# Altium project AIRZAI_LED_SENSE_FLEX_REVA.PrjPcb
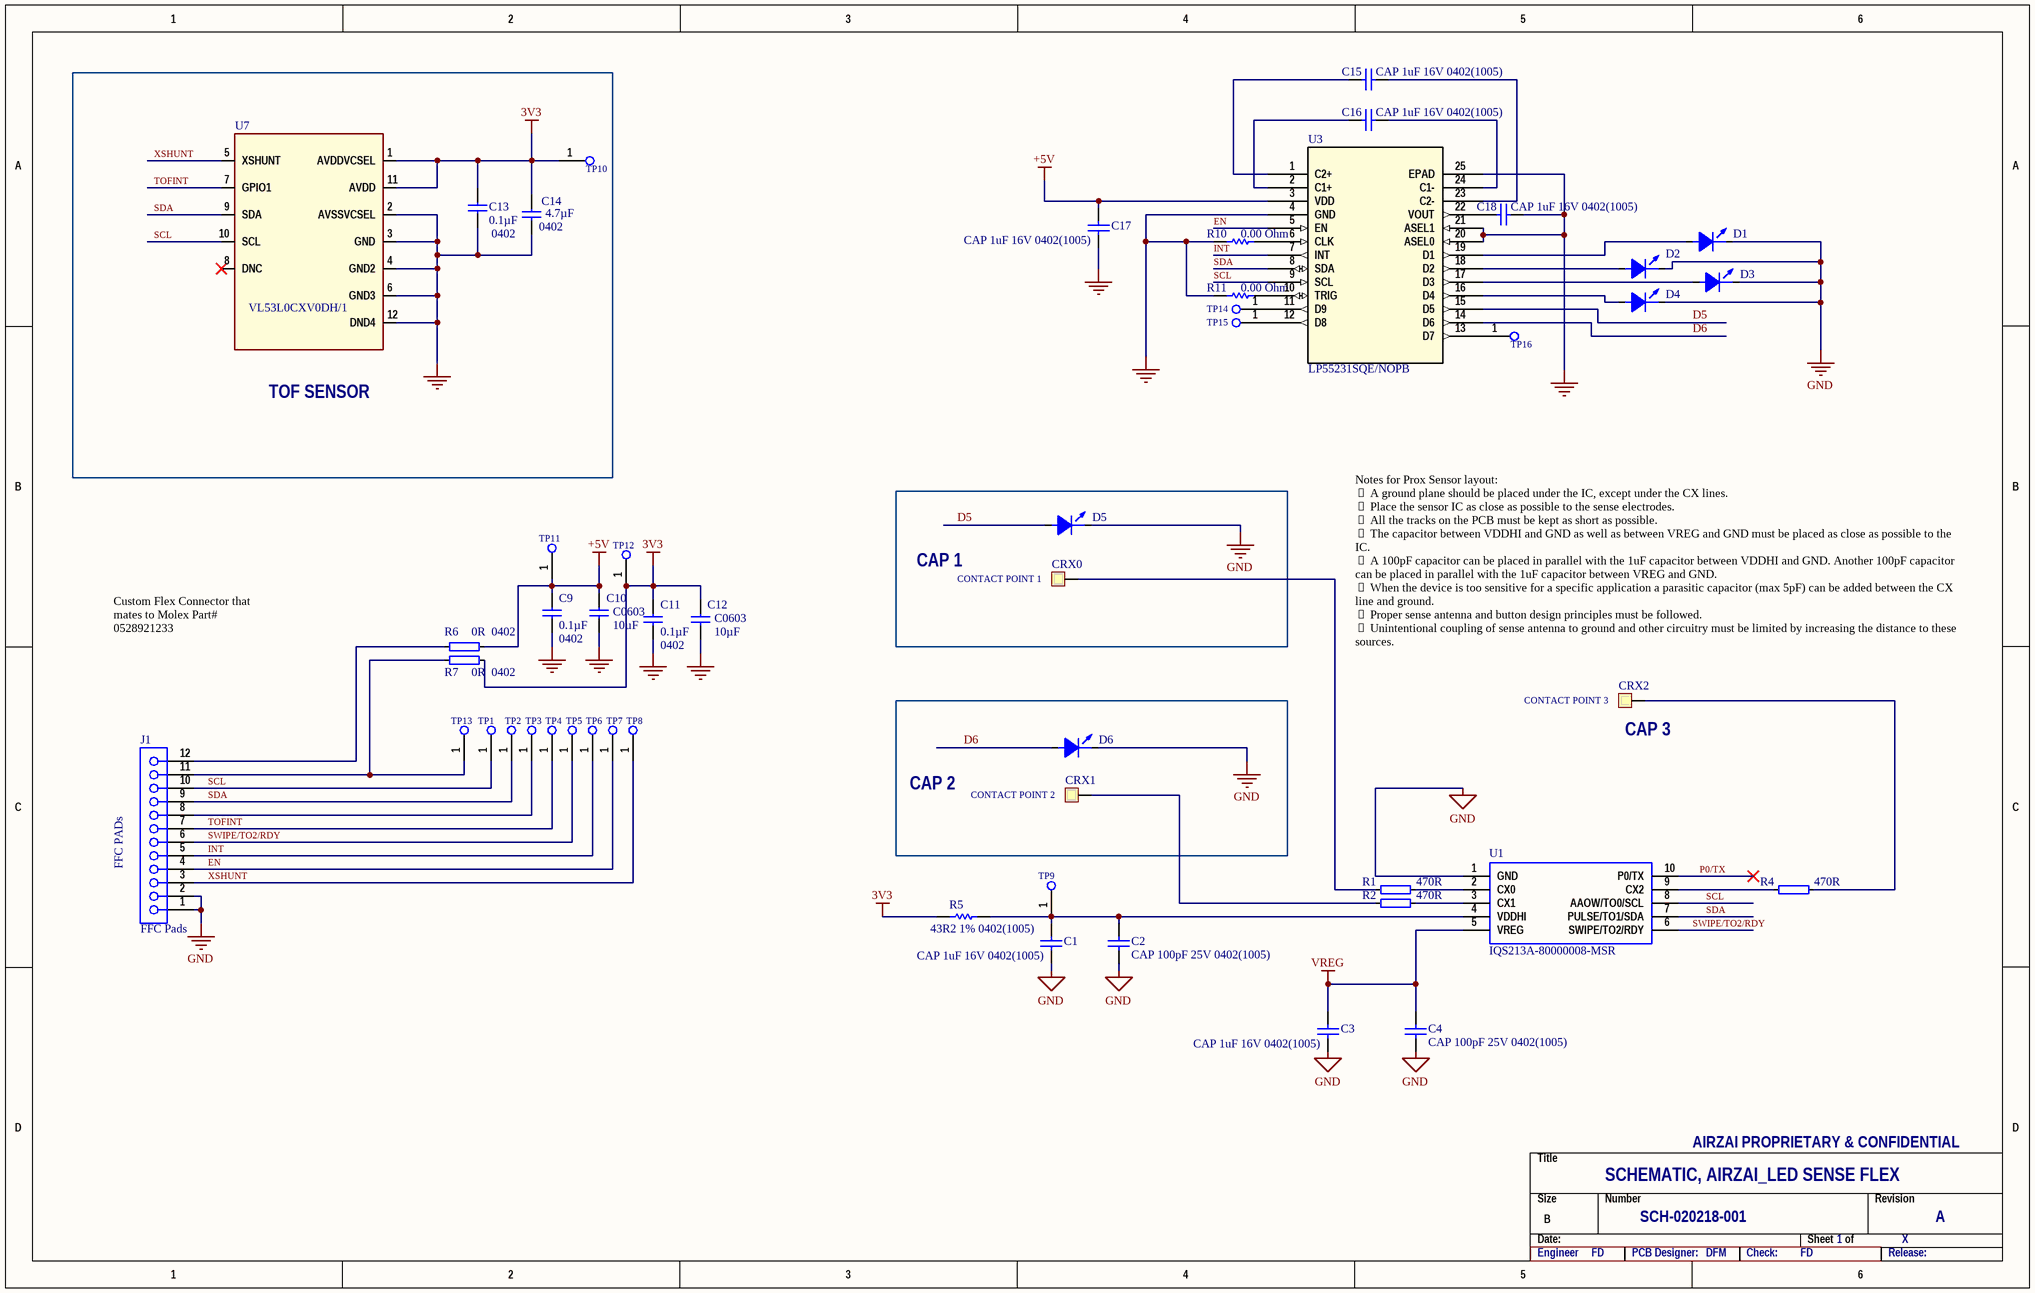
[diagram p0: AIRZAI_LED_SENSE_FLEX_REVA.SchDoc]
1 sheet, 51 parts. Net scope: global (net labels, ports and power ports of the same name join across sheets).
Board file: AIRZAI_LED_SENSE_FLEX_REVA.PcbDoc

## Sheet AIRZAI_LED_SENSE_FLEX_REVA.SchDoc
size B

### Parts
C1  CAP 1uF 16V 0402(1005)  [0402-A]
C2  CAP 100pF 25V 0402(1005)  [0402-A]
C3  CAP 1uF 16V 0402(1005)  [0402-A]
C4  CAP 100pF 25V 0402(1005)  [0402-A]
C9  0.1µF  Footprint: 0402  [0402CAP]
C10  10µF  Footprint: C0603  [0603]
C11  0.1µF  Footprint: 0402  [0402CAP]
C12  10µF  Footprint: C0603  [0603]
C13  0.1µF  Footprint: 0402  [0402CAP]
C14  4.7µF  Footprint: 0402  [0603]
C15  CAP 1uF 16V 0402(1005)  [CAPC0402(1005)60_M]
C16  CAP 1uF 16V 0402(1005)  [CAPC0402(1005)60_M]
C17  CAP 1uF 16V 0402(1005)  [CAPC0402(1005)60_M]
C18  CAP 1uF 16V 0402(1005)  [CAPC0402(1005)60_M]
CRX0  CONTACT POINT 1  [CONTACT_POINT_1CM _SQ]
CRX1  CONTACT POINT 2  [CONTACT_POINT_1CM _SQ]
CRX2  CONTACT POINT 3  [CONTACT_POINT_0.7CM]
D1  WHITE  [LED1206_LTW-C230DS]  (value not drawn)
D2  WHITE  [LED1206_LTW-C230DS]  (value not drawn)
D3  WHITE  [LED1206_LTW-C230DS]  (value not drawn)
D4  WHITE  [LED1206_LTW-C230DS]  (value not drawn)
D5  WHITE  [LED1206_LTW-C230DS]  (value not drawn)
D6  WHITE  [LED1206_LTW-C230DS]  (value not drawn)
J1  FFC Pads  [FFC_Pads]
R1  470R  [0402-A]
R2  470R  [0402-A]
R4  470R  [0402-A]
R5  43R2 1% 0402(1005)  [0402-A]
R6  0R  [0402]
R7  0R  [0402]
R10  value 0.00 Ohm  [0402]  (hidden comment: Jumper 0402(1005))
R11  value 0.00 Ohm  [0402]  (hidden comment: Jumper 0402(1005))
TP1  Test Point  [TP_0.9MM]  (value not drawn)
TP2  Test Point  [TP_0.9MM]  (value not drawn)
TP3  Test Point  [TP_0.9MM]  (value not drawn)
TP4  Test Point  [TP_0.9MM]  (value not drawn)
TP5  Test Point  [TP_0.9MM]  (value not drawn)
TP6  Test Point  [TP_0.9MM]  (value not drawn)
TP7  Test Point  [TP_0.9MM]  (value not drawn)
TP8  Test Point  [TP_0.9MM]  (value not drawn)
TP9  Test Point  [TP_0.9MM]  (value not drawn)
TP10  Test Point  [TP_0.9MM]  (value not drawn)
TP11  Test Point  [TP_0.9MM]  (value not drawn)
TP12  Test Point  [TP_0.9MM]  (value not drawn)
TP13  Test Point  [TP_0.9MM]  (value not drawn)
TP14  Test Point  [TP_0.9MM]  (value not drawn)
TP15  Test Point  [TP_0.9MM]  (value not drawn)
TP16  Test Point  [TP_0.9MM]  (value not drawn)
U1  IQS213A-80000008-MSR  [MSOP-10-IQS213A-80000008-MSR]
U3  LP55231SQE/NOPB  [WQFN-24-LP55231SQE/NOPB]
U7  VL53L0CXV0DH/1  [VL53L0X]

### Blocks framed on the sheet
TOF SENSOR: C13 C14 TP10 U7
CAP 1: CRX0 D5
CAP 2: CRX1 D6

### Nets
3V3: C11.1 C12.1 C13.1 C14.2 R5.1 R7.1 TP10.1 TP12.1 U7.1(AVDDVCSEL) U7.11(AVDD)
+5V: C9.1 C10.1 C17.2 R6.1 TP11.1 U3.3(VDD)
GND: C1.1 C2.1 C3.1 C4.1 C9.2 C10.2 C11.2 C12.2 C13.2 C14.1 C17.1 C18.2 D1.1(CATHODE) D2.1(CATHODE) D3.1(CATHODE) D4.1(CATHODE) D5.1(CATHODE) D6.1(CATHODE) J1.1 J1.2 R10.1 R11.1 U1.1(GND) U3.4(GND) U3.20(ASEL0) U3.21(ASEL1) U3.25(EPAD) U7.2(AVSSVCSEL) U7.3(GND) U7.4(GND2) U7.6(GND3) U7.12(DND4)
VREG: C3.2 C4.2 U1.5(VREG)
D5: D5.2(ANODE) U3.15(D5)
D6: D6.2(ANODE) U3.14(D6)
EN: J1.4 TP7.1 U3.5(EN)
INT: J1.5 TP6.1 U3.7(INT)
P0/TX: U1.10(P0/TX)
SCL: J1.10 TP1.1 U1.8(AAOW/TO0/SCL) U3.9(SCL) U7.10(SCL)
SDA: J1.9 TP2.1 U1.7(PULSE/TO1/SDA) U3.8(SDA) U7.9(SDA)
SWIPE/TO2/RDY: J1.6 TP5.1 U1.6(SWIPE/TO2/RDY)
TOFINT: J1.7 TP4.1 U7.7(GPIO1)
XSHUNT: J1.3 TP8.1 U7.5(XSHUNT)
NetC1_2: C1.2 C2.2 R5.2 TP9.1 U1.4(VDDHI)
NetC15_1: C15.1 U3.1(C2+)
NetC15_2: C15.2 U3.23(C2-)
NetC16_1: C16.1 U3.2(C1+)
NetC16_2: C16.2 U3.24(C1-)
NetC18_1: C18.1 U3.22(VOUT)
NetCRX0_1: CRX0.1 R1.2
NetCRX1_1: CRX1.1 R2.2
NetCRX2_1: CRX2.1 R4.1
NetD1_2: D1.2(ANODE) U3.19(D1)
NetD2_2: D2.2(ANODE) U3.18(D2)
NetD3_2: D3.2(ANODE) U3.17(D3)
NetD4_2: D4.2(ANODE) U3.16(D4)
NetJ1_8: J1.8 TP3.1
NetJ1_11: J1.11 R7.2 TP13.1
NetJ1_12: J1.12 R6.2
NetR1_1: R1.1 U1.2(CX0)
NetR2_1: R2.1 U1.3(CX1)
NetR4_2: R4.2 U1.9(CX2)
NetR10_2: R10.2 U3.6(CLK)
NetR11_2: R11.2 U3.10(TRIG)
NetTP14_1: TP14.1 U3.11(D9)
NetTP15_1: TP15.1 U3.12(D8)
NetTP16_1: TP16.1 U3.13(D7)

Not connected (* = marked no-connect by the designer): U7 8(DNC)*

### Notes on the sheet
- Custom Flex Connector that mates to Molex Part# 0528921233
- (near CRX2) Notes for Prox Sensor layout:
   A ground plane should be placed under the IC, except under the CX lines.
   Place the sensor IC as close as possible to the sense electrodes.
   All the tracks on the PCB must be kept as short as possible.
   The capacitor between VDDHI and GND as well as between VREG and GND must be placed as close as possible to the IC.
   A 100pF capacitor can be placed in parallel with the 1uF capacitor between VDDHI and GND. Another 100pF capacitor can be placed in parallel with the 1uF capacitor between VREG and GND.
   When the device is too sensitive for a specific application a parasitic capacitor (max 5pF) can be added between the CX line and ground.
   Proper sense antenna and button design principles must be followed.
   Unintentional coupling of sense antenna to ground and other circuitry must be limited by increasing the distance to these sources.
- (near CRX2) CAP 3
- (near J1) FFC PADs
- SCHEMATIC, AIRZAI_LED SENSE FLEX
- AIRZAI PROPRIETARY & CONFIDENTIAL
- SCH-020218-001
- 1
- X
- A
- Engineer
- FD
- PCB Designer:
- DFM
- Check:
- Release:

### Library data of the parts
C1 C3 C15-C18 = CAP: CAP 1uF 16V ±10% 0402 (1005 Metric) Thickness 0.6mm SMD; Case-EIA: 0402; Tolerance: Â±10%; Case-Metric: 1005
C2 C4 = CAP: CAP 100pF 25V ±2% 0402 (1005 Metric) Thickness 0.6mm SMD; Tolerance: Â±2%; Case-Metric: 1005; Case-EIA: 0402
C9 C11 C13 = C0402-100n: Capacitor, X7R, ±10%; Manufacturer: TDK; Manufacturer Part Number: C1005X7R1C104K; Note: 16V ±10% X7R; Case-Metric: 1005; Rated Voltage: 16 V; Tolerance: Â±20%
C10 C12 = C0402-100n: Capacitor, X7R, ±10%; Manufacturer: MURATA; Manufacturer Part Number: GRM188R60J106ME47D; Note: 6.3volts X5R 20%; Case-Metric: 1608; Rated Voltage: 6.3 V; Tolerance: Â±20%
C14 = C0603-1µ0 X7R: Capacitor, X7R, ±10%; Manufacturer: TDK; Manufacturer Part Number: C1005X5R0J475M; Case-Metric: 1005; Note: 6.3volts X5R 20%; Rated Voltage: 6.3 V; Tolerance: Â±20%
CRX0-CRX2 = WIRE_POINT
D1-D6 = LED_LTW-C230DS: Manufacturer: LITEON; Note: REVERSE MOUNT CHIP LED
J1 = FFC_PADS: 0.5 mm Pitch FFC Pads
R1 R2 R4 = R0402-12k: Resistor, ±1%, 0.063W; Manufacturer: Panasonic; Manufacturer Part Number: ERJ-2RKF4700X; Case-EIA: 0402; Case-Metric: 1005
R5 = RES: 43R2 0.063W 1% 0402 (1005 Metric)  SMD; Case-Metric: 1005; Case-EIA: 0402; Value: 43.20 Ohm
R6 R7 = R0402-12k: Resistor, ±1%, 0.063W; Manufacturer: Panasonic; Manufacturer Part Number: ERJ-2GE0R00X; Note: 0.1W JUMPER; Case-Metric: 1005; Tolerance: None
R10 R11 = RES: Jumper 0402 (1005 Metric); Tolerance: None; Case-Metric: 1005
U1 = IQS213A-80000008-MSR: Capacitive Touch Sensors 3 Ch Capacitive Touch/Swipe Function; Manufacturer_Name: Azoteq; Geometry.Height: 1.05mm
U3 = LP55231SQE/NOPB: Imported; Vendor: Texas Instruments; Built_By: EMA_UL_Team; C: Copyright (C) 2016 Accelerated Designs. All rights reserved
U7 = VL53L0X: Manufacturer: ST; Case-EIA: LGA12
